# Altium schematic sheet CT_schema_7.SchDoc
size 254 x 194 mm
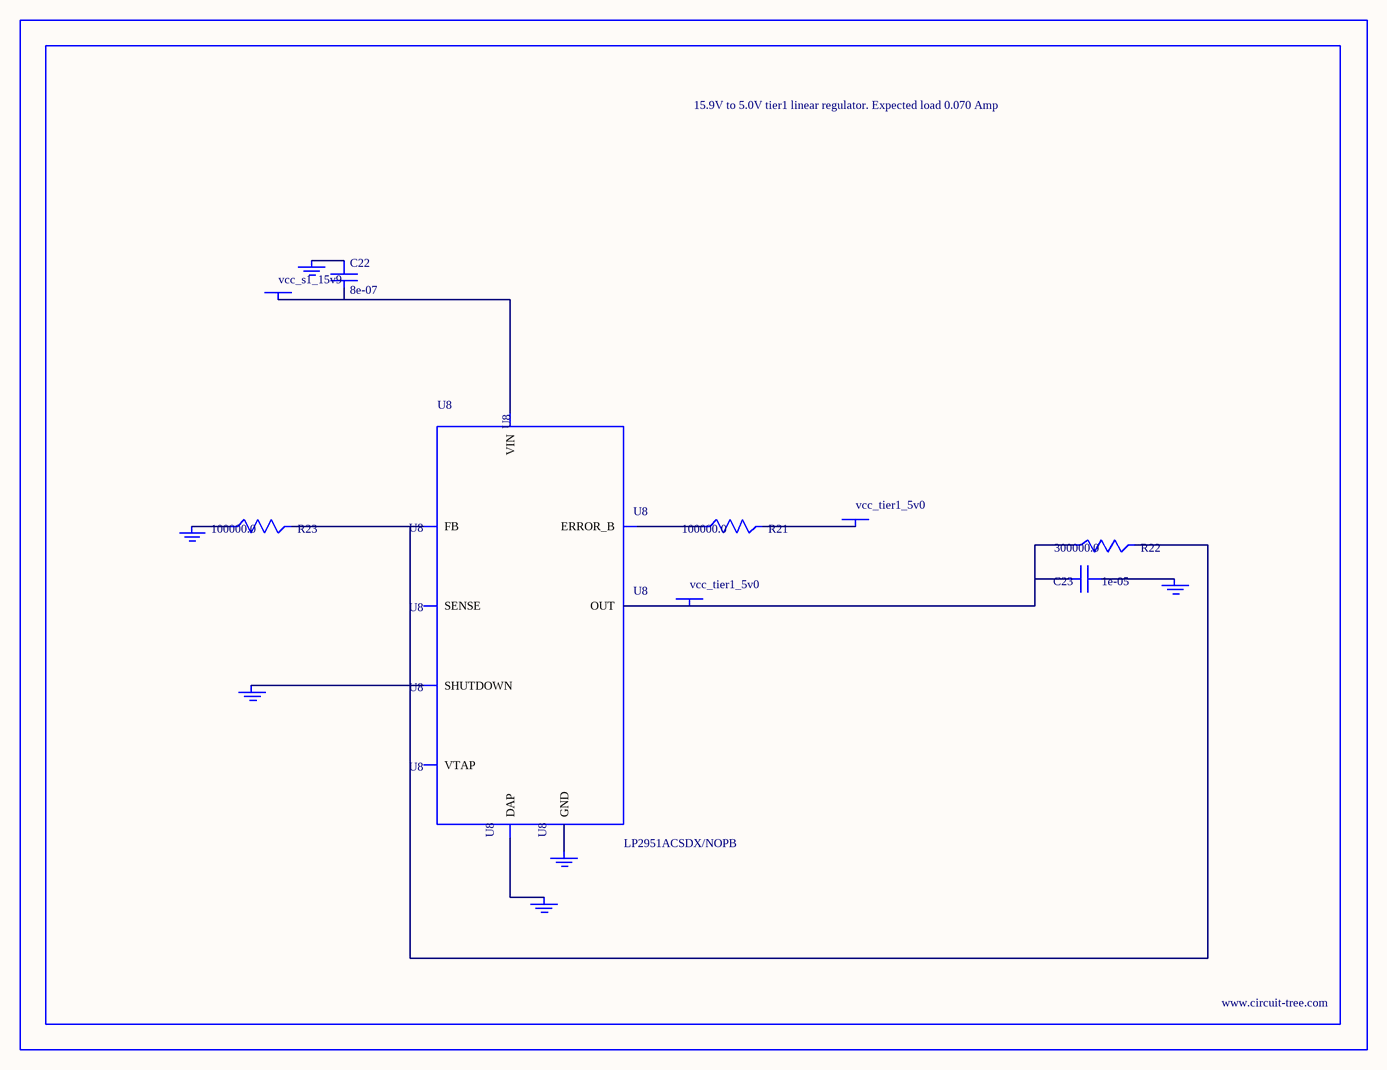
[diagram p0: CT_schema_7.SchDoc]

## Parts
BORDER6  (no value)
C22  8e-07  [R0603]
C23  1e-05  [C1210]
GND_INSTANCE_6_0  (no value)
GND_INSTANCE_6_1  (no value)
GND_INSTANCE_6_2  (no value)
GND_INSTANCE_6_3  (no value)
GND_INSTANCE_6_4  (no value)
GND_INSTANCE_6_5  (no value)
POWER_INSTANCE_6_0  vcc_tier1_5v0
POWER_INSTANCE_6_1  vcc_s1_15v9
POWER_INSTANCE_6_2  vcc_tier1_5v0
R21  100000.0  [R0603]
R22  300000.0  [R0603]
R23  100000.0  [R0603]
U8  LP2951ACSDX/NOPB  [WSON-8]

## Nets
NetC22_1: C22.1 GND_INSTANCE_6_3.0(GND)
NetC22_2: C22.2 POWER_INSTANCE_6_1.0(PWR) U8.8(VIN)
NetC23_1: C23.1 GND_INSTANCE_6_0.0(GND)
NetC23_2: C23.2 POWER_INSTANCE_6_2.0(PWR) R22.1 U8.1(OUT)
NetGND_INSTANCE_6_1_0: GND_INSTANCE_6_1.0(GND) U8.3(SHUTDOWN)
NetGND_INSTANCE_6_2_0: GND_INSTANCE_6_2.0(GND) R23.1
NetGND_INSTANCE_6_4_0: GND_INSTANCE_6_4.0(GND) U8.PAD(DAP)
NetGND_INSTANCE_6_5_0: GND_INSTANCE_6_5.0(GND) U8.4(GND)
NetPOWER_INSTANCE_6_0_0: POWER_INSTANCE_6_0.0(PWR) R21.2
NetR21_1: R21.1 U8.5(ERROR_B)
NetR22_2: R22.2 R23.2 U8.7(FB)

Not connected (* = marked no-connect by the designer): U8 2(SENSE) 6(VTAP)

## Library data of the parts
BORDER6 = BORDER_PAGE6
C22 = C22
C23 = GRM32DR61E106MA12L
GND_INSTANCE_6_0-GND_INSTANCE_6_5 = GND
POWER_INSTANCE_6_0-POWER_INSTANCE_6_2 = PWR
R21 R23 = RC0603JR-07100KL
R22 = RC0603JR-07300KL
